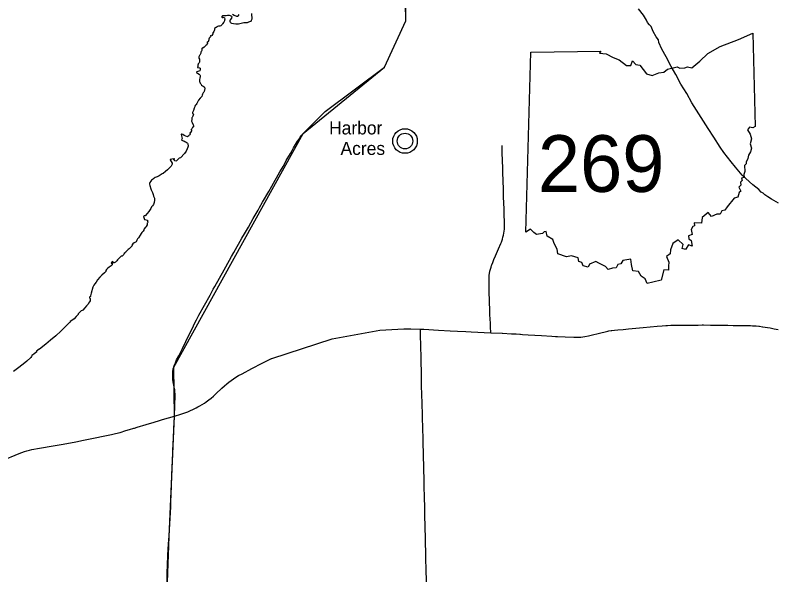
# Model space of a CAD drawing. Extents: x -82 to 873, y 0 to 440.
# Drawn here: x 461.2 to 521.9, y 170.9 to 215.6 of the extents above; entities that cross this region are included whole.
import ezdxf

# ---------------------------------------------------------------- set-up
doc = ezdxf.new("R2010")
doc.units = 0
for name, color, linetype in [('DV_X_Corp_Line', 7, 'Continuous'), ('GM_P_US_Alignment', 7, 'Continuous'), ('GM_X_County', 7, 'Continuous'), ('GM_X_Interstate_Route', 7, 'Continuous'), ('PV_P_Text', 7, 'Continuous')]:
    doc.layers.add(name, color=color, linetype=linetype)

msp = doc.modelspace()

# ---------------------------------------------------------------- linework, layer by layer
at = {"layer": 'DV_X_Corp_Line'}
for radius in [0.982, 0.623]:
    msp.add_circle((492.376, 205.586), radius, dxfattribs=at)
at = {"layer": 'GM_P_US_Alignment'}
msp.add_lwpolyline([(473.365, 168.87), (473.535, 173.991), (473.96, 183.618), (473.906, 187.531), (484.23, 206.176), (490.737, 211.48), (492.433, 215.185), (491.986, 239.02), (491.811, 239.475), (491.569, 239.636), (491.322, 239.672), (489.332, 239.581), (489.281, 240.625)], dxfattribs=at)
at = {"layer": 'GM_X_County'}
for points in [[(522.202, 200.621), (521.653, 200.944), (521.348, 201.136), (521.121, 201.288), (520.972, 201.416), (520.819, 201.508), (520.638, 201.71), (520.145, 202.093), (519.291, 202.87), (518.762, 203.497), (518.422, 203.93), (517.826, 204.667), (517.531, 205.1), (517.042, 205.884), (516.581, 206.579), (515.84, 207.77), (515.289, 208.635), (514.878, 209.383), (514.406, 210.132), (513.99, 210.895), (513.638, 211.548), (513.219, 212.312), (512.871, 212.929), (512.655, 213.447), (512.619, 213.664), (512.442, 213.912), (512.201, 214.334), (512.034, 214.738), (511.889, 214.859), (511.736, 215.057), (511.662, 215.241), (511.42, 215.635), (511.034, 216.153)], [(480.118, 215.76), (480.137, 215.326), (480.124, 215.26), (480.098, 215.224), (480.077, 215.165), (480.042, 215.136), (479.88, 215.069), (479.766, 215.039), (479.652, 215.029), (479.535, 215.029), (479.513, 215.016), (479.087, 214.932), (478.86, 214.924), (478.667, 214.948), (478.559, 214.964), (478.495, 214.996), (478.457, 215.026), (478.429, 215.065), (478.419, 215.121), (478.409, 215.168), (478.409, 215.196), (478.419, 215.232), (478.442, 215.269), (478.533, 215.403), (478.559, 215.441), (478.564, 215.486), (478.535, 215.54), (478.499, 215.568), (478.436, 215.598), (478.364, 215.607), (478.298, 215.618), (478.187, 215.613), (478.08, 215.6), (478.011, 215.585), (477.886, 215.583), (477.824, 215.595), (477.791, 215.589), (477.765, 215.568), (477.742, 215.525), (477.755, 215.473), (477.783, 215.451), (477.823, 215.452), (477.856, 215.467), (477.898, 215.462), (477.947, 215.421), (477.974, 215.326), (477.973, 215.247), (477.948, 215.186), (477.898, 215.07), (477.809, 214.948), (477.784, 214.896), (477.749, 214.857), (477.667, 214.794), (477.59, 214.768), (477.489, 214.754), (477.414, 214.741), (477.365, 214.703), (477.288, 214.667), (477.237, 214.617), (477.174, 214.567), (477.163, 214.543), (477.16, 214.458), (477.144, 214.392), (477.112, 214.325), (477.058, 214.248), (477.023, 214.228), (477.021, 214.188), (477.016, 214.152), (476.961, 214.019), (476.896, 213.955), (476.871, 213.985), (476.855, 213.988), (476.823, 213.946), (476.831, 213.91), (476.789, 213.852), (476.743, 213.816), (476.718, 213.712), (476.709, 213.662), (476.695, 213.58), (476.656, 213.523), (476.615, 213.494), (476.599, 213.506), (476.573, 213.493), (476.571, 213.452), (476.585, 213.427), (476.592, 213.357), (476.573, 213.312), (476.542, 213.278), (476.475, 213.223), (476.404, 213.151), (476.341, 213.08), (476.222, 213.008), (476.183, 212.997), (476.157, 212.987), (476.151, 212.955), (476.147, 212.919), (476.137, 212.815), (476.114, 212.764), (476.086, 212.733), (476.063, 212.668), (476.068, 212.608), (475.999, 212.455), (475.958, 212.407), (475.929, 212.371), (475.911, 212.299), (475.917, 212.213), (475.963, 212.112), (475.971, 212.055), (475.968, 211.957), (475.974, 211.893), (475.942, 211.84), (475.911, 211.794), (475.877, 211.782), (475.865, 211.746), (475.848, 211.704), (475.827, 211.664), (475.831, 211.575), (475.831, 211.502), (475.807, 211.484), (475.812, 211.463), (475.972, 211.421), (476.005, 211.402), (476.019, 211.365), (476.019, 211.33), (476.005, 211.298), (475.998, 211.199), (475.746, 211.112), (475.716, 211.096), (475.714, 211.07), (475.792, 211.008), (475.942, 210.927), (476.002, 210.868), (476.022, 210.828), (476.022, 210.803), (476.014, 210.737), (475.984, 210.604), (475.957, 210.513), (475.962, 210.442), (475.976, 210.346), (475.999, 210.285), (476.028, 210.221), (476.072, 210.143), (476.132, 210.06), (476.213, 209.993), (476.268, 209.963), (476.301, 209.939), (476.319, 209.905), (476.356, 209.874), (476.386, 209.822), (476.389, 209.771), (476.342, 209.553), (476.302, 209.481), (476.251, 209.424), (476.194, 209.339), (476.167, 209.249), (476.149, 209.154), (476.095, 209.101), (476.005, 209.011), (475.896, 208.852), (475.815, 208.699), (475.751, 208.582), (475.694, 208.511), (475.65, 208.456), (475.602, 208.381), (475.553, 208.277), (475.536, 208.213), (475.472, 208.036), (475.434, 207.931), (475.416, 207.854), (475.415, 207.821), (475.436, 207.794), (475.466, 207.77), (475.478, 207.731), (475.467, 207.664), (475.438, 207.573), (475.415, 207.51), (475.388, 207.474), (475.35, 207.445), (475.361, 207.386), (475.352, 207.302), (475.337, 207.175), (475.373, 207.07), (475.461, 206.867), (475.489, 206.828), (475.489, 206.779), (475.476, 206.728), (475.442, 206.693), (475.415, 206.68), (475.393, 206.649), (475.388, 206.601), (475.36, 206.562), (475.336, 206.532), (475.302, 206.512), (475.302, 206.487), (475.323, 206.467), (475.328, 206.426), (475.314, 206.395), (475.254, 206.272), (475.24, 206.246), (475.204, 206.246), (475.19, 206.207), (475.206, 206.189), (475.22, 206.143), (475.183, 206.077), (475.14, 206.042), (475.105, 206.008), (475.045, 205.941), (474.993, 205.911), (474.729, 206.038), (474.633, 206.097), (474.557, 206.134), (474.532, 206.134), (474.506, 206.095), (474.582, 205.787), (474.541, 205.737), (474.536, 205.693), (474.566, 205.65), (474.612, 205.627), (474.665, 205.606), (474.708, 205.59), (474.74, 205.579), (474.759, 205.56), (474.789, 205.535), (474.839, 205.526), (474.86, 205.505), (474.894, 205.489), (474.986, 205.455), (475.013, 205.425), (475.041, 205.363), (475.055, 205.184), (475.039, 205.092), (474.984, 204.953), (474.89, 204.778), (474.759, 204.597), (474.435, 204.251), (474.338, 204.209), (474.114, 203.996), (474.073, 203.982), (474.006, 204), (473.965, 204.035), (473.922, 204.092), (473.912, 204.106), (473.935, 204.115), (473.954, 204.131), (473.965, 204.154), (473.935, 204.163), (473.903, 204.147), (473.88, 204.147), (473.853, 204.159), (473.649, 204.122), (473.616, 204.108), (473.614, 204.081), (473.768, 203.815), (473.791, 203.755), (473.782, 203.725), (473.692, 203.587), (473.539, 203.418), (473.412, 203.296), (473.261, 203.149), (473.071, 203.005), (472.993, 202.963), (472.743, 202.817), (472.589, 202.739), (472.419, 202.663), (472.353, 202.615), (472.298, 202.557), (472.213, 202.525), (472.142, 202.466), (472.075, 202.392), (472.004, 202.28), (471.97, 202.197), (471.965, 202.128), (472.002, 202.027), (472.073, 201.775), (472.096, 201.692), (472.137, 201.621), (472.201, 201.486), (472.266, 201.323), (472.271, 201.279), (472.28, 201.229), (472.298, 201.183), (472.362, 201.032), (472.378, 200.947), (472.378, 200.867), (472.337, 200.683), (472.279, 200.529), (472.22, 200.422), (472.137, 200.328), (472.084, 200.183), (471.926, 199.965), (471.791, 199.802), (471.612, 199.619), (471.587, 199.616), (471.538, 199.616), (471.506, 199.591), (471.493, 199.57), (471.493, 199.545), (471.575, 199.325), (471.6, 199.311), (471.802, 199.252), (471.818, 199.197), (471.828, 199.109), (471.818, 199.052), (471.795, 199.036), (471.773, 198.997), (471.791, 198.965), (471.782, 198.896), (471.743, 198.802), (471.734, 198.765), (471.688, 198.717), (471.658, 198.717), (471.557, 198.574), (471.529, 198.504), (471.527, 198.453), (471.47, 198.375), (471.364, 198.267), (471.302, 198.196), (471.221, 198.058), (471.087, 197.845), (471.011, 197.76), (470.97, 197.678), (470.922, 197.577), (470.899, 197.536), (470.846, 197.497), (470.75, 197.465), (470.65, 197.379), (470.582, 197.292), (470.557, 197.267), (470.587, 197.205), (470.357, 196.978), (470.259, 196.919), (470.087, 196.737), (470.061, 196.691), (469.954, 196.597), (469.91, 196.529), (469.786, 196.4), (469.713, 196.379), (469.499, 196.187), (469.428, 196.093), (469.364, 196.019), (469.247, 195.921), (469.149, 195.856), (469.054, 195.861), (469.031, 195.886), (469.073, 195.934), (469.036, 195.953), (468.917, 195.847), (468.937, 195.808), (468.986, 195.833), (469.002, 195.808), (469.002, 195.737), (468.988, 195.698), (468.901, 195.622), (468.759, 195.503), (468.619, 195.402), (468.536, 195.313), (468.495, 195.248), (468.476, 195.173), (468.38, 195.056), (468.153, 194.884), (467.995, 194.723), (467.825, 194.503), (467.713, 194.324), (467.595, 194.19), (467.522, 194.071), (467.437, 193.913), (467.3, 193.438), (467.265, 193.218), (467.252, 193.179), (467.208, 193.145), (467.18, 193.108), (467.183, 193.067), (467.229, 192.998), (467.236, 192.892), (467.233, 192.83), (467.187, 192.734), (467.107, 192.631), (467.084, 192.555), (466.953, 192.408), (466.813, 192.261), (466.635, 192.064), (466.605, 192.059), (466.518, 192.025), (466.277, 191.773), (466.272, 191.729), (466.125, 191.58), (465.942, 191.385), (465.841, 191.316), (465.637, 191.161), (465.637, 191.128), (465.591, 191.084), (464.894, 190.41), (464.483, 190.034), (464.075, 189.683), (463.687, 189.355), (463.188, 188.956), (463.173, 188.971), (462.942, 188.788), (462.939, 188.744), (462.939, 188.719), (462.898, 188.68), (462.73, 188.547), (462.648, 188.494), (462.566, 188.478), (462.57, 188.43), (462.549, 188.373), (462.485, 188.304), (462.178, 188.012), (461.887, 187.767), (461.426, 187.409), (461.323, 187.341), (461.104, 187.182)], [(478.591, 215.716), (478.745, 215.631), (478.926, 215.565), (478.973, 215.564), (479.021, 215.57), (479.071, 215.586), (479.091, 215.611), (479.131, 215.693)]]:
    msp.add_lwpolyline(points, dxfattribs=at)
at = {"layer": 'GM_X_Interstate_Route'}
for points in [[(486.004, 207.946), (490.737, 211.48), (492.433, 215.185), (492.437, 218.22)], [(474.021, 185.389), (474.004, 185.552), (473.982, 185.7), (473.968, 185.796), (473.917, 186.079), (473.866, 186.361), (473.843, 186.523), (473.829, 186.686), (473.823, 186.85), (473.823, 187.013), (473.83, 187.135), (473.846, 187.256), (473.852, 187.291), (473.869, 187.376), (473.906, 187.531), (473.946, 187.652), (473.987, 187.767), (474.034, 187.88), (474.139, 188.102), (474.306, 188.431), (474.612, 189.012), (474.882, 189.565), (475.252, 190.343), (475.45, 190.751), (475.488, 190.831), (475.574, 191.007), (475.719, 191.301), (475.912, 191.663), (476.804, 193.279), (477.065, 193.744), (477.188, 193.966), (477.561, 194.641), (477.921, 195.286), (478.364, 196.072), (478.527, 196.357), (478.717, 196.694), (479.356, 197.821), (479.559, 198.177), (479.864, 198.711), (480.252, 199.388), (480.639, 200.064), (480.761, 200.281), (481.003, 200.707), (481.492, 201.561), (481.735, 201.989), (482.386, 203.129), (482.437, 203.217), (482.632, 203.555), (482.773, 203.8), (482.897, 204.018), (483.222, 204.582), (483.368, 204.836), (483.482, 205.034), (483.798, 205.582), (483.806, 205.595), (483.884, 205.721), (484, 205.89), (484.098, 206.02), (484.148, 206.079), (484.23, 206.176), (484.341, 206.296), (485.099, 207.046), (485.211, 207.155), (485.275, 207.218), (485.305, 207.246), (485.913, 207.857), (486.004, 207.946)], [(500.297, 199.768), (500.283, 200.152), (500.253, 201.119), (500.232, 201.77), (500.211, 202.391), (500.203, 202.654), (500.197, 202.843), (500.181, 203.409), (500.144, 204.633), (500.132, 205.119), (500.128, 205.236)], [(499.098, 193.773), (499.089, 194.248), (499.091, 194.51), (499.094, 194.7), (499.107, 194.861), (499.128, 195.017), (499.155, 195.179), (499.192, 195.342), (499.247, 195.522), (499.293, 195.656), (499.304, 195.687), (499.38, 195.887), (499.474, 196.115), (499.605, 196.416), (499.854, 196.979), (500.029, 197.395), (500.07, 197.5), (500.102, 197.586), (500.153, 197.741), (500.198, 197.899), (500.236, 198.058), (500.267, 198.219), (500.291, 198.381), (500.308, 198.543), (500.318, 198.707), (500.32, 198.87), (500.318, 199.096), (500.318, 199.117), (500.298, 199.721), (500.297, 199.768)], [(499.23, 190.265), (499.214, 190.748), (499.206, 190.985), (499.171, 191.401), (499.153, 191.683), (499.14, 192.014), (499.121, 192.789), (499.102, 193.563), (499.098, 193.773)], [(481.737, 188.221), (486.563, 189.778), (490.362, 190.47), (492.281, 190.591)], [(492.281, 190.591), (492.623, 190.586)], [(492.623, 190.586), (492.84, 190.582), (493.614, 190.567)], [(493.614, 190.567), (493.882, 190.554), (495.037, 190.49), (495.971, 190.435), (496.579, 190.402)], [(494.011, 173.828), (494.011, 173.828), (493.968, 175.699), (493.955, 176.314), (493.936, 177.133), (493.915, 177.994), (493.913, 178.116), (493.905, 178.445), (493.824, 181.559), (493.812, 181.969), (493.8, 182.482), (493.773, 183.649), (493.743, 184.672), (493.722, 185.322), (493.705, 186.064), (493.689, 186.968), (493.655, 188.109), (493.627, 189.385), (493.619, 189.918), (493.614, 190.175), (493.614, 190.567)], [(500.142, 190.226), (500.153, 190.226), (500.891, 190.195), (501.219, 190.182), (501.24, 190.18), (501.554, 190.16), (501.588, 190.158), (501.768, 190.144), (502.202, 190.111), (503.267, 190.039), (504.087, 189.996), (504.395, 189.981), (504.542, 189.974), (505.153, 189.945), (505.85, 189.915), (506.096, 189.909), (506.187, 189.91), (506.26, 189.911), (506.423, 189.922), (506.586, 189.94), (506.747, 189.965), (507.029, 190.021), (507.229, 190.066), (507.904, 190.242), (508.463, 190.376), (508.585, 190.402), (508.665, 190.416), (508.827, 190.44), (508.89, 190.447), (509.114, 190.471), (509.374, 190.495), (509.805, 190.536), (510.232, 190.576), (510.504, 190.601), (511.403, 190.683), (512.516, 190.788), (512.915, 190.826), (513.21, 190.847), (513.325, 190.855), (513.613, 190.866), (513.833, 190.869), (514.329, 190.874), (514.852, 190.881), (515.144, 190.884), (515.584, 190.889), (515.794, 190.89), (516.099, 190.891), (516.2, 190.892), (516.777, 190.885), (517.596, 190.875), (518.067, 190.866), (518.145, 190.865), (518.581, 190.858), (518.868, 190.853), (519.977, 190.838), (520.113, 190.833), (520.264, 190.827), (520.428, 190.815), (520.639, 190.791), (520.673, 190.787), (520.927, 190.751), (520.958, 190.747), (521.314, 190.69), (521.526, 190.657), (521.849, 190.596), (522.171, 190.529)], [(496.579, 190.402), (497.231, 190.366), (497.647, 190.345), (499.23, 190.265)], [(499.23, 190.265), (500.142, 190.226)], [(473.96, 183.618), (474.484, 183.775), (474.717, 183.851), (475.03, 183.962), (475.253, 184.057), (475.433, 184.135), (475.586, 184.208), (475.699, 184.264), (475.839, 184.341), (476.002, 184.435), (476.359, 184.655), (476.499, 184.748), (476.708, 184.904), (476.901, 185.057), (477.087, 185.217), (477.268, 185.383), (477.741, 185.838), (477.953, 186.032), (478.14, 186.193), (478.3, 186.321), (478.489, 186.463), (478.497, 186.469), (478.667, 186.586), (478.875, 186.718), (479.087, 186.844), (479.375, 187.002), (480.136, 187.404), (480.974, 187.838), (481.707, 188.207), (481.737, 188.221)], [(473.96, 183.618), (473.967, 183.845), (473.986, 184.22), (474.001, 184.637), (474.027, 185.1), (474.027, 185.265), (474.021, 185.388), (474.021, 185.389)], [(460.161, 180.033), (461.56, 180.623), (461.788, 180.714), (461.982, 180.78), (462.178, 180.839), (462.376, 180.891), (462.576, 180.933), (463.181, 181.043), (464.274, 181.227), (464.92, 181.345), (465.364, 181.426), (466.089, 181.565), (466.693, 181.684), (467.377, 181.823), (468.544, 182.057), (468.945, 182.143), (469.265, 182.22), (469.622, 182.316), (470.094, 182.455), (470.363, 182.536), (470.723, 182.646), (470.763, 182.658), (470.983, 182.724), (471.717, 182.938), (472.336, 183.125), (472.762, 183.253), (473.004, 183.329), (473.96, 183.618)], [(473.535, 173.991), (473.577, 174.564), (473.634, 175.466), (473.671, 176.368), (473.686, 176.779), (473.706, 177.353), (473.785, 179.568), (473.807, 180.019), (473.835, 180.757), (473.867, 181.496), (473.875, 181.778), (473.914, 182.641), (473.931, 183.037), (473.96, 183.618)], [(473.372, 169.382), (473.374, 169.563), (473.375, 169.768), (473.379, 170.22), (473.388, 171.123), (473.402, 171.697), (473.434, 172.476), (473.465, 173.009), (473.518, 173.745), (473.535, 173.991)], [(494.117, 169.605), (494.098, 170.291), (494.093, 170.577), (494.068, 171.191), (494.038, 172.379), (494.011, 173.828)]]:
    msp.add_lwpolyline(points, dxfattribs=at)
at = {"layer": 'PV_P_Text'}
msp.add_line((502.031, 198.317), (502.431, 212.68), dxfattribs=at)
msp.add_line((502.031, 198.317), (502.431, 212.68), dxfattribs=at)
for points in [[(502.431, 212.68), (508.004, 212.774), (507.917, 212.6), (508.443, 212.564), (509.002, 212.257), (509.474, 212.063), (510.052, 211.607), (510.397, 211.612), (510.544, 211.986), (510.808, 211.697), (511.123, 211.646), (511.666, 210.958), (512.114, 210.809), (512.651, 211.045), (513.053, 211.084), (513.346, 211.317), (514.111, 211.516), (514.324, 211.397), (514.729, 211.421), (514.933, 211.509), (515.286, 211.43), (515.908, 211.953), (516.547, 212.568), (517.531, 213.15), (519.002, 213.7), (520.164, 214.192), (520.333, 206.739)], [(502.431, 212.68), (508.004, 212.774), (507.917, 212.6), (508.443, 212.564), (509.002, 212.257), (509.474, 212.063), (510.052, 211.607), (510.397, 211.612), (510.544, 211.986), (510.808, 211.697), (511.123, 211.646), (511.666, 210.958), (512.114, 210.809), (512.651, 211.045), (513.053, 211.084), (513.346, 211.317), (514.111, 211.516), (514.324, 211.397), (514.729, 211.421), (514.933, 211.509), (515.286, 211.43), (515.908, 211.953), (516.547, 212.568), (517.531, 213.15), (519.002, 213.7), (520.164, 214.192), (520.333, 206.739)], [(520.333, 206.739), (520.161, 206.634), (519.894, 206.684), (519.714, 206.475), (519.937, 206.126), (520.042, 205.757), (519.949, 205.351), (520.04, 205.016), (519.978, 204.736), (519.81, 204.457), (519.752, 204.191), (519.61, 203.91), (519.622, 203.754), (519.485, 203.629), (519.51, 203.163), (519.441, 202.905), (519.465, 202.682), (519.244, 202.624), (519.295, 202.439), (519.155, 202.297), (519.185, 202.052), (519.025, 201.896), (519.18, 201.584), (519.056, 201.484), (518.953, 201.104), (518.67, 201.027), (518.103, 200.331), (517.903, 200.069), (517.679, 200.003), (517.555, 199.733), (517.278, 199.732), (516.86, 199.545), (516.589, 199.867), (516.115, 199.479), (516.06, 199.031), (515.461, 199.045), (515.484, 198.819), (515.351, 198.753), (515.229, 198.526), (515.299, 198.123), (515.019, 198.02), (515.053, 197.786), (515.233, 197.643), (515.313, 197.196), (515.014, 197.287), (514.77, 196.91), (514.519, 196.998), (514.601, 197.317), (514.177, 197.701), (513.775, 197.394), (513.565, 196.902), (513.563, 196.572), (513.264, 196.372), (513.456, 195.905), (513.421, 195.583), (513.427, 195.277), (513.052, 195.288), (512.826, 194.463)], [(520.333, 206.739), (520.161, 206.634), (519.894, 206.684), (519.714, 206.475), (519.937, 206.126), (520.042, 205.757), (519.949, 205.351), (520.04, 205.016), (519.978, 204.736), (519.81, 204.457), (519.752, 204.191), (519.61, 203.91), (519.622, 203.754), (519.485, 203.629), (519.51, 203.163), (519.441, 202.905), (519.465, 202.682), (519.244, 202.624), (519.295, 202.439), (519.155, 202.297), (519.185, 202.052), (519.025, 201.896), (519.18, 201.584), (519.056, 201.484), (518.953, 201.104), (518.67, 201.027), (518.103, 200.331), (517.903, 200.069), (517.679, 200.003), (517.555, 199.733), (517.278, 199.732), (516.86, 199.545), (516.589, 199.867), (516.115, 199.479), (516.06, 199.031), (515.461, 199.045), (515.484, 198.819), (515.351, 198.753), (515.229, 198.526), (515.299, 198.123), (515.019, 198.02), (515.053, 197.786), (515.233, 197.643), (515.313, 197.196), (515.014, 197.287), (514.77, 196.91), (514.519, 196.998), (514.601, 197.317), (514.177, 197.701), (513.775, 197.394), (513.565, 196.902), (513.563, 196.572), (513.264, 196.372), (513.456, 195.905), (513.421, 195.583), (513.427, 195.277), (513.052, 195.288), (512.826, 194.463)], [(512.826, 194.463), (512.176, 194.306), (511.724, 194.211), (511.565, 194.586), (511.242, 194.783), (511.032, 195.161), (510.568, 195.212), (510.459, 195.73), (510.407, 196.15), (509.773, 196.046), (509.599, 195.789), (509.374, 195.72), (509.244, 195.461), (508.937, 195.44), (508.609, 195.318), (508.393, 195.571), (507.855, 195.826), (507.613, 195.958), (507.106, 195.754), (506.998, 195.512), (506.595, 195.618), (506.5, 195.888), (506.256, 195.969), (506.202, 196.255), (505.681, 196.407), (505.282, 196.347), (504.579, 196.577), (504.536, 196.953), (504.296, 197.412), (504.171, 197.73), (503.726, 197.973), (503.636, 198.352), (503.494, 198.341), (503.364, 198.187), (502.87, 198.117), (502.673, 198.271), (502.396, 198.535), (502.031, 198.317)], [(512.826, 194.463), (512.176, 194.306), (511.724, 194.211), (511.565, 194.586), (511.242, 194.783), (511.032, 195.161), (510.568, 195.212), (510.459, 195.73), (510.407, 196.15), (509.773, 196.046), (509.599, 195.789), (509.374, 195.72), (509.244, 195.461), (508.937, 195.44), (508.609, 195.318), (508.393, 195.571), (507.855, 195.826), (507.613, 195.958), (507.106, 195.754), (506.998, 195.512), (506.595, 195.618), (506.5, 195.888), (506.256, 195.969), (506.202, 196.255), (505.681, 196.407), (505.282, 196.347), (504.579, 196.577), (504.536, 196.953), (504.296, 197.412), (504.171, 197.73), (503.726, 197.973), (503.636, 198.352), (503.494, 198.341), (503.364, 198.187), (502.87, 198.117), (502.673, 198.271), (502.396, 198.535), (502.031, 198.317)]]:
    msp.add_lwpolyline(points, dxfattribs=at)

# ---------------------------------------------------------------- texts
at = {"layer": 'DV_X_Corp_Line'}
for s, p in [('Harbor', (486.311, 206.113)), ('Acres', (487.224, 204.475))]:
    msp.add_text(s, height=1.0417, rotation=0.00501, dxfattribs=at).set_placement(p)
at = {"layer": 'PV_P_Text'}
msp.add_text('269', height=4.5281, rotation=0.005, dxfattribs=at).set_placement((502.988, 201.52))

doc.saveas('drawing.dxf')
